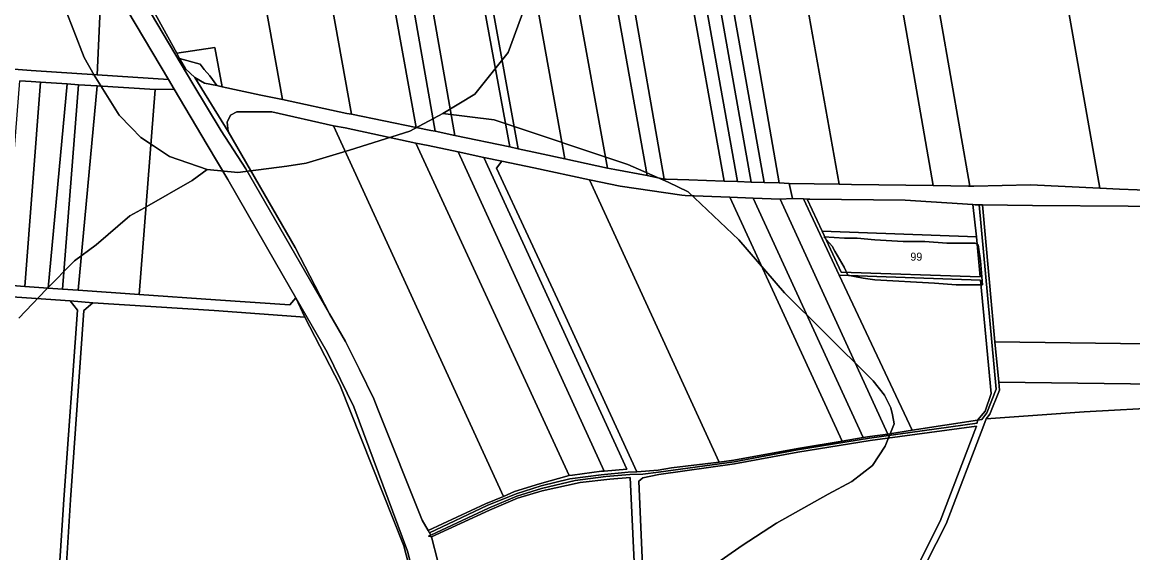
# Model space of a CAD drawing. Extents: x -541351 to -537540, y -1162694 to -1159725.
# Drawn here: x -539563 to -538870, y -1161525 to -1161193 of the extents above; entities that cross this region are included whole.
import ezdxf

# ---------------------------------------------------------------- set-up
doc = ezdxf.new("R2010")
doc.units = 0
for name, color, linetype in [('95560013', 7, 'Continuous'), ('95590013', 7, 'Continuous'), ('95610013', 7, 'Continuous'), ('95640013', 7, 'Continuous'), ('95660013', 7, 'Continuous')]:
    doc.layers.add(name, color=color, linetype=linetype)

msp = doc.modelspace()

# ---------------------------------------------------------------- linework, layer by layer
at = {"layer": '95560013'}
for points in [[(-538994.31, -1161295.03), (-539045.37, -1161294.34), (-539053.1, -1161294.23), (-539103, -1161013.98), (-539095.66, -1161011.59), (-539087.45, -1161008.9), (-539043.01, -1161015.07)], [(-539118.78, -1161021.38), (-539119.66, -1161019.55), (-539103, -1161013.98), (-539053.1, -1161294.23), (-539084.18, -1161293.8), (-539090.47, -1161293.43), (-539136.75, -1161027.11)], [(-538972.25, -1161295.43), (-538994.31, -1161295.03), (-539043.01, -1161015.07), (-539019.68, -1161018.63), (-538971.53, -1161295.41)], [(-539154.11, -1161033.45), (-539146.43, -1161030.83), (-539099.9, -1161293.1), (-539108, -1161292.84)], [(-539090.47, -1161293.43), (-539099.9, -1161293.1), (-539146.43, -1161030.83), (-539136.75, -1161027.11)], [(-539116.49, -1161292.48), (-539124.88, -1161292.22), (-539170.2, -1161038.79), (-539162.3, -1161036.06)], [(-539108, -1161292.84), (-539116.49, -1161292.48), (-539162.3, -1161036.06), (-539154.11, -1161033.45)], [(-539146.97, -1161291.52), (-539161.16, -1161290.98), (-539162.36, -1161290.96), (-539204.4, -1161050.02), (-539191.17, -1161045.44), (-539170.2, -1161038.79), (-539124.88, -1161292.22)], [(-539212.36, -1161052.68), (-539204.4, -1161050.02), (-539162.36, -1161290.96), (-539173.01, -1161288.87), (-539215.11, -1161053.62)], [(-539238.1, -1161061.49), (-539215.11, -1161053.62), (-539173.01, -1161288.87), (-539193.16, -1161285.12), (-539197.72, -1161284.19)], [(-538844.86, -1161298.63), (-538877.93, -1161297.24), (-538890.19, -1161296.72), (-538931.09, -1161065.09), (-538897.58, -1161075.44), (-538883.22, -1161083.36)], [(-539261.83, -1161069.68), (-539224.32, -1161278.28), (-539240.79, -1161274.83), (-539253.51, -1161272.15), (-539287.68, -1161083.7), (-539284.33, -1161077.27)], [(-539292.9, -1161085.27), (-539298.4, -1161081.63), (-539284.33, -1161077.27), (-539287.68, -1161083.7), (-539253.51, -1161272.15), (-539258.85, -1161270.91)], [(-539298.4, -1161081.63), (-539292.9, -1161085.27), (-539258.85, -1161270.91), (-539293.08, -1161263.8), (-539323.99, -1161088.08)], [(-539305.49, -1161261.12), (-539308.15, -1161260.59), (-539317.28, -1161258.8), (-539346.97, -1161094.08), (-539335.13, -1161091.14)], [(-539293.08, -1161263.8), (-539305.49, -1161261.12), (-539335.13, -1161091.14), (-539323.99, -1161088.08)], [(-539384.02, -1161103.38), (-539346.97, -1161094.08), (-539317.28, -1161258.8), (-539357.66, -1161250.4)], [(-539398.81, -1161106.88), (-539384.02, -1161103.38), (-539357.66, -1161250.4), (-539360.48, -1161249.96), (-539400.77, -1161241.37), (-539423.77, -1161112.8)], [(-539414.3, -1161238.64), (-539438.49, -1161233.39), (-539443.01, -1161208.8), (-539466.8, -1161212.37), (-539481.41, -1161185.77), (-539498.11, -1161150.86), (-539503.79, -1161133.46), (-539423.77, -1161112.8), (-539400.77, -1161241.37)], [(-539516.59, -1161225.93), (-539513.32, -1161157.12), (-539497.36, -1161186), (-539472.01, -1161228.75)], [(-539446.12, -1161226.55), (-539449.58, -1161222.58), (-539452.22, -1161219.18), (-539464.98, -1161215.56), (-539466.8, -1161212.37), (-539443.01, -1161208.8), (-539438.49, -1161233.39), (-539441.79, -1161232.59)], [(-539551.82, -1161230.45), (-539561.62, -1161358.04), (-539574.79, -1161357.02), (-539564.86, -1161229.58), (-539557.83, -1161230.05)], [(-539547.15, -1161359.17), (-539561.62, -1161358.04), (-539551.82, -1161230.45), (-539535.3, -1161231.55)], [(-539528.25, -1161232.02), (-539538.26, -1161359.87), (-539547.15, -1161359.17), (-539535.3, -1161231.55)], [(-539516.42, -1161232.77), (-539528.28, -1161360.42), (-539538.26, -1161359.87), (-539528.25, -1161232.02)], [(-539490.23, -1161363.16), (-539528.28, -1161360.42), (-539516.42, -1161232.77), (-539480.24, -1161235.04)], [(-539396.15, -1161369.7), (-539442.69, -1161366.45), (-539490.23, -1161363.16), (-539480.24, -1161235.04), (-539468.39, -1161234.85), (-539447.73, -1161269.69), (-539434.98, -1161291.19), (-539405.14, -1161343.09), (-539392.4, -1161365.24)], [(-539343.67, -1161428.41), (-539352.75, -1161410.03), (-539361.37, -1161392.57), (-539371.3, -1161375.32), (-539392.78, -1161333.67), (-539434.61, -1161261.23), (-539435.27, -1161255.47), (-539433.29, -1161251.13), (-539429.24, -1161248.96), (-539407.44, -1161249.02), (-539368.8, -1161257.67), (-539262.79, -1161489.32), (-539274.05, -1161494.04), (-539309.76, -1161510.68), (-539313.61, -1161504.16), (-539341.16, -1161434.73)], [(-539361.55, -1161258.93), (-539317.48, -1161268.47), (-539221.6, -1161476.34), (-539240.12, -1161481.39), (-539255.82, -1161486.31), (-539262.79, -1161489.32), (-539368.8, -1161257.67)], [(-539201.42, -1161473.62), (-539219.53, -1161475.95), (-539221.6, -1161476.34), (-539317.48, -1161268.47), (-539309.77, -1161269.96), (-539291.06, -1161274.07), (-539199.83, -1161473.45)], [(-539274.89, -1161277.57), (-539185.77, -1161472.36), (-539199.83, -1161473.45), (-539291.06, -1161274.07)], [(-539221.38, -1161478.29), (-539239.09, -1161482.82), (-539254.81, -1161487.62), (-539272.91, -1161495.1), (-539308.92, -1161512.11), (-539309.76, -1161510.68), (-539274.05, -1161494.04), (-539262.79, -1161489.32), (-539255.82, -1161486.31), (-539240.12, -1161481.39), (-539221.6, -1161476.34), (-539219.53, -1161475.95), (-539201.42, -1161473.62), (-539199.83, -1161473.45), (-539185.77, -1161472.36), (-539274.89, -1161277.57), (-539263.85, -1161279.74), (-539266.98, -1161284.14), (-539227.53, -1161369.24), (-539179.43, -1161473.91), (-539184.82, -1161474.17), (-539201.65, -1161475.75)], [(-539243.86, -1161284.07), (-539208.93, -1161291.41), (-539128, -1161467.95), (-539157.73, -1161471.56), (-539166.1, -1161473.03), (-539179.43, -1161473.91), (-539227.53, -1161369.24), (-539266.98, -1161284.14), (-539263.85, -1161279.74)], [(-539208.93, -1161291.41), (-539189.79, -1161295.41), (-539151.41, -1161301.15), (-539149.32, -1161301.23), (-539121.44, -1161302.27), (-539051.27, -1161454.8), (-539077.65, -1161459.24), (-539078.79, -1161459.42), (-539118.8, -1161466.6), (-539128, -1161467.95)], [(-539121.44, -1161302.27), (-539106.85, -1161302.97), (-539038.01, -1161452.55), (-539051.27, -1161454.8)], [(-539038.01, -1161452.55), (-539106.85, -1161302.97), (-539089.91, -1161303.49), (-539022.72, -1161450.38), (-539033.96, -1161451.91)], [(-538965.62, -1161307.06), (-538954.91, -1161422.36), (-538960.73, -1161437.13), (-538963.9, -1161441.23), (-538966.6, -1161441.62), (-538961.82, -1161436.03), (-538958.01, -1161424.97), (-538964.8, -1161354.15), (-539053.06, -1161351.04), (-539075.23, -1161303.45), (-539072.96, -1161303.55), (-539063.59, -1161323.62), (-539051.76, -1161349.11), (-538965.08, -1161352.17), (-538967.33, -1161327.07), (-538969.5, -1161306.98), (-538968, -1161307.03), (-538967.65, -1161307.04)], [(-539063.59, -1161323.62), (-539072.96, -1161303.55), (-539071.39, -1161303.57), (-539011.91, -1161304.22), (-538969.5, -1161306.98), (-538967.33, -1161327.07)], [(-538932.3, -1161307.52), (-538872.55, -1161307.97), (-538818.82, -1161309.45), (-538763.94, -1161310.7), (-538783.09, -1161395.05), (-538955.74, -1161392.63), (-538963.6, -1161307.09)], [(-538966.6, -1161441.62), (-539007.49, -1161447.85), (-539053.06, -1161351.04), (-538964.8, -1161354.15), (-538958.01, -1161424.97), (-538961.82, -1161436.03)], [(-539533.39, -1161367.17), (-539528.83, -1161372.95), (-539537.3, -1161491.19), (-539540.03, -1161532.85), (-539540.59, -1161537.62), (-539542.08, -1161542.6), (-539563.48, -1161597.18), (-539577.88, -1161634.94), (-539584.99, -1161637.27), (-539619.67, -1161612.02), (-539611.41, -1161487.28), (-539603.07, -1161362.24)], [(-539535.76, -1161531.54), (-539533.06, -1161491.37), (-539524.83, -1161373.04), (-539519.3, -1161368.27), (-539443.35, -1161373.22), (-539386.7, -1161377.26), (-539364.89, -1161419.69), (-539325.02, -1161520.27), (-539316.47, -1161553.16), (-539393.88, -1161548.37), (-539475.24, -1161542.78), (-539531.17, -1161538.46)], [(-538953.42, -1161417.83), (-538955.74, -1161392.63), (-538783.09, -1161395.05), (-538788.75, -1161420.02)], [(-538846.86, -1161433.5), (-538900.02, -1161436.5), (-538961.19, -1161440.84), (-538958.99, -1161437.99), (-538952.96, -1161422.9), (-538953.42, -1161417.83), (-538788.75, -1161420.02), (-538792.05, -1161434.55)], [(-539238.9, -1161484.33), (-539254.44, -1161489.15), (-539272.18, -1161496.58), (-539308.09, -1161513.51), (-539308.92, -1161512.11), (-539272.91, -1161495.1), (-539254.81, -1161487.62), (-539239.09, -1161482.82), (-539221.38, -1161478.29), (-539201.65, -1161475.75), (-539184.82, -1161474.17), (-539179.43, -1161473.91), (-539166.1, -1161473.03), (-539157.73, -1161471.56), (-539128, -1161467.95), (-539118.8, -1161466.6), (-539078.79, -1161459.42), (-539077.65, -1161459.24), (-539051.27, -1161454.8), (-539038.01, -1161452.55), (-539033.96, -1161451.91), (-539022.72, -1161450.38), (-539007.49, -1161447.85), (-538966.6, -1161441.62), (-538966.95, -1161443.49), (-539034.08, -1161452.94), (-539079.12, -1161460.2), (-539118.59, -1161467.64), (-539165.9, -1161474.14), (-539175.74, -1161475.47), (-539183.71, -1161475.65), (-539198.73, -1161476.82), (-539217.94, -1161479.48)], [(-539165.77, -1161475.73), (-539118.49, -1161469.02), (-539078.91, -1161461.6), (-539033.77, -1161454.46), (-538967.29, -1161445.36), (-538990.03, -1161504.88), (-539002.3, -1161529.1), (-539029.85, -1161572.32), (-539076.14, -1161579.22), (-539114.95, -1161586), (-539172.72, -1161546.83), (-539175.52, -1161542.03), (-539178.27, -1161479.78), (-539175.58, -1161477.66)], [(-539303.69, -1161529.93), (-539307.78, -1161514.67), (-539271.36, -1161497.96), (-539253.99, -1161490.48), (-539238.57, -1161485.84), (-539214.9, -1161480.72), (-539196.33, -1161478.48), (-539183.57, -1161477.43), (-539180.21, -1161547.75), (-539143.02, -1161572.92), (-539286.85, -1161613.44), (-539291.53, -1161590.26), (-539295.77, -1161569.23), (-539302.55, -1161535.61)]]:
    msp.add_lwpolyline(points, close=True, dxfattribs=at)
for points in [[(-539180.21, -1161547.75), (-539183.57, -1161477.43), (-539196.33, -1161478.48), (-539214.9, -1161480.72), (-539238.57, -1161485.84), (-539253.99, -1161490.48), (-539271.36, -1161497.96), (-539307.78, -1161514.67), (-539309.47, -1161514.21), (-539308.09, -1161513.51), (-539272.18, -1161496.58), (-539254.44, -1161489.15), (-539238.9, -1161484.33), (-539217.94, -1161479.48), (-539198.73, -1161476.82), (-539183.71, -1161475.65), (-539175.74, -1161475.47), (-539165.9, -1161474.14), (-539118.59, -1161467.64), (-539079.12, -1161460.2), (-539034.08, -1161452.94), (-538966.95, -1161443.49), (-538966.6, -1161441.62), (-538963.9, -1161441.23), (-538960.73, -1161437.13), (-538954.91, -1161422.36), (-538965.62, -1161307.06), (-538963.6, -1161307.09), (-538955.74, -1161392.63), (-538953.42, -1161417.83), (-538952.96, -1161422.9), (-538958.99, -1161437.99), (-538961.19, -1161440.84), (-538962.68, -1161444.73), (-538986.28, -1161506.51), (-538998.73, -1161531.09)], [(-539540.03, -1161532.85), (-539537.3, -1161491.19), (-539528.83, -1161372.95), (-539533.39, -1161367.17), (-539519.3, -1161368.27), (-539524.83, -1161373.04), (-539533.06, -1161491.37), (-539535.76, -1161531.54)], [(-538744.9, -1161566.45), (-538909.04, -1161586.11), (-538945.39, -1161587.98), (-538982.39, -1161591.84), (-539060.53, -1161602.73), (-539085.19, -1161606.18), (-539114.95, -1161586), (-539076.14, -1161579.22), (-539029.85, -1161572.32), (-539024.51, -1161571.52), (-538998.73, -1161531.09), (-538986.28, -1161506.51), (-538962.68, -1161444.73), (-538961.19, -1161440.84), (-538900.02, -1161436.5), (-538846.86, -1161433.5)], [(-539002.3, -1161529.1), (-538990.03, -1161504.88), (-538967.29, -1161445.36), (-539033.77, -1161454.46), (-539078.91, -1161461.6), (-539118.49, -1161469.02), (-539165.77, -1161475.73), (-539175.58, -1161477.66), (-539178.27, -1161479.78), (-539175.52, -1161542.03)]]:
    msp.add_lwpolyline(points, dxfattribs=at)
at = {"layer": '95590013'}
for points in [[(-539513.32, -1161157.12), (-539516.59, -1161225.93), (-539557.69, -1161223.11), (-539601.36, -1161219.9), (-539597.06, -1161137.85), (-539549.61, -1161136.48), (-539524.21, -1161145.9)], [(-538965.08, -1161352.17), (-539051.76, -1161349.11), (-539063.59, -1161323.62), (-538967.33, -1161327.07)]]:
    msp.add_lwpolyline(points, close=True, dxfattribs=at)
at = {"layer": '95610013'}
for points in [[(-538933.47, -1161294.66), (-538968.85, -1161295.34), (-538971.53, -1161295.41), (-539019.68, -1161018.63), (-539013.52, -1161019.58), (-538938.47, -1161062.83), (-538931.09, -1161065.09), (-538890.19, -1161296.72)], [(-539261.83, -1161069.68), (-539238.1, -1161061.49), (-539197.72, -1161284.19), (-539224.32, -1161278.28)], [(-539082.25, -1161303.24), (-539075.23, -1161303.45), (-539053.06, -1161351.04), (-539007.49, -1161447.85), (-539022.72, -1161450.38), (-539089.91, -1161303.49)]]:
    msp.add_lwpolyline(points, close=True, dxfattribs=at)
at = {"layer": '95640013'}
for points in [[(-539579.46, -1160855.53), (-539546.37, -1160976.85), (-539518.85, -1161082.11), (-539509.83, -1161115.28), (-539506.91, -1161125.99), (-539502.19, -1161143.36), (-539486.6, -1161181.18), (-539456.83, -1161231.51), (-539439.15, -1161260.76), (-539423.55, -1161284.51), (-539371.3, -1161375.32), (-539361.37, -1161392.57), (-539352.75, -1161410.03), (-539343.67, -1161428.41), (-539341.16, -1161434.73), (-539313.61, -1161504.16), (-539309.76, -1161510.68), (-539308.92, -1161512.11), (-539308.09, -1161513.51), (-539309.47, -1161514.21), (-539307.78, -1161514.67), (-539303.69, -1161529.93)], [(-539297.21, -1161624.42), (-539322.59, -1161523.59), (-539356.24, -1161433.35), (-539372.91, -1161399.14), (-539392.4, -1161365.24), (-539405.14, -1161343.09), (-539434.98, -1161291.19), (-539447.73, -1161269.69), (-539468.39, -1161234.85), (-539472.01, -1161228.75), (-539497.36, -1161186), (-539521.39, -1161121.63), (-539531.01, -1161084.78), (-539557.57, -1160980.12), (-539590.55, -1160859.01)], [(-539601.36, -1161219.9), (-539557.69, -1161223.11), (-539516.59, -1161225.93), (-539472.01, -1161228.75), (-539468.39, -1161234.85), (-539480.24, -1161235.04), (-539516.42, -1161232.77), (-539528.25, -1161232.02), (-539535.3, -1161231.55), (-539551.82, -1161230.45), (-539557.83, -1161230.05), (-539564.86, -1161229.58)], [(-538818.82, -1161309.45), (-538872.55, -1161307.97), (-538932.3, -1161307.52), (-538963.6, -1161307.09), (-538965.62, -1161307.06), (-538967.65, -1161307.04), (-538968, -1161307.03), (-538969.5, -1161306.98), (-539011.91, -1161304.22), (-539071.39, -1161303.57), (-539072.96, -1161303.55), (-539075.23, -1161303.45), (-539082.25, -1161303.24), (-539084.18, -1161293.8), (-539053.1, -1161294.23), (-539045.37, -1161294.34), (-538994.31, -1161295.03), (-538972.25, -1161295.43), (-538971.53, -1161295.41), (-538968.85, -1161295.34), (-538933.47, -1161294.66), (-538890.19, -1161296.72), (-538877.93, -1161297.24), (-538844.86, -1161298.63)], [(-539574.79, -1161357.02), (-539561.62, -1161358.04), (-539547.15, -1161359.17), (-539538.26, -1161359.87), (-539528.28, -1161360.42), (-539490.23, -1161363.16), (-539442.69, -1161366.45), (-539396.15, -1161369.7), (-539392.4, -1161365.24), (-539386.7, -1161377.26), (-539443.35, -1161373.22), (-539519.3, -1161368.27), (-539533.39, -1161367.17), (-539603.07, -1161362.24)]]:
    msp.add_lwpolyline(points, dxfattribs=at)
for points in [[(-539439.15, -1161260.76), (-539456.83, -1161231.51), (-539486.6, -1161181.18), (-539502.19, -1161143.36), (-539506.91, -1161125.99), (-539503.79, -1161133.46), (-539498.11, -1161150.86), (-539481.41, -1161185.77), (-539466.8, -1161212.37), (-539464.98, -1161215.56), (-539461.28, -1161222.06), (-539455.45, -1161227.46), (-539434.61, -1161261.23), (-539392.78, -1161333.67), (-539371.3, -1161375.32), (-539423.55, -1161284.51)], [(-539452.22, -1161219.18), (-539449.58, -1161222.58), (-539446.12, -1161226.55), (-539441.79, -1161232.59), (-539449.57, -1161231.06), (-539455.45, -1161227.46), (-539461.28, -1161222.06), (-539464.98, -1161215.56)], [(-539434.61, -1161261.23), (-539455.45, -1161227.46), (-539449.57, -1161231.06), (-539441.79, -1161232.59), (-539438.49, -1161233.39), (-539414.3, -1161238.64), (-539400.77, -1161241.37), (-539360.48, -1161249.96), (-539357.66, -1161250.4), (-539317.28, -1161258.8), (-539308.15, -1161260.59), (-539305.49, -1161261.12), (-539293.08, -1161263.8), (-539258.85, -1161270.91), (-539253.51, -1161272.15), (-539240.79, -1161274.83), (-539224.32, -1161278.28), (-539197.72, -1161284.19), (-539193.16, -1161285.12), (-539173.01, -1161288.87), (-539162.36, -1161290.96), (-539161.16, -1161290.98), (-539146.97, -1161291.52), (-539124.88, -1161292.22), (-539116.49, -1161292.48), (-539108, -1161292.84), (-539099.9, -1161293.1), (-539090.47, -1161293.43), (-539084.18, -1161293.8), (-539082.25, -1161303.24), (-539089.91, -1161303.49), (-539106.85, -1161302.97), (-539121.44, -1161302.27), (-539149.32, -1161301.23), (-539151.41, -1161301.15), (-539189.79, -1161295.41), (-539208.93, -1161291.41), (-539243.86, -1161284.07), (-539263.85, -1161279.74), (-539274.89, -1161277.57), (-539291.06, -1161274.07), (-539309.77, -1161269.96), (-539317.48, -1161268.47), (-539361.55, -1161258.93), (-539368.8, -1161257.67), (-539407.44, -1161249.02), (-539429.24, -1161248.96), (-539433.29, -1161251.13), (-539435.27, -1161255.47)], [(-539306.78, -1161596.54), (-539315.76, -1161556.43), (-539316.47, -1161553.16), (-539325.02, -1161520.27), (-539364.89, -1161419.69), (-539386.7, -1161377.26), (-539392.4, -1161365.24), (-539372.91, -1161399.14), (-539356.24, -1161433.35), (-539322.59, -1161523.59), (-539297.21, -1161624.42), (-539291.45, -1161636.72), (-539299.04, -1161627.81), (-539305.07, -1161603.34)]]:
    msp.add_lwpolyline(points, close=True, dxfattribs=at)
at = {"layer": '95660013'}
for points in [[(-539249.12, -1161183), (-539259.87, -1161212), (-539280.62, -1161238), (-539300.5, -1161250), (-539321.19, -1161261), (-539358.87, -1161273), (-539386, -1161281), (-539398.12, -1161283), (-539428.69, -1161287), (-539447.81, -1161285), (-539471.37, -1161277), (-539481.27, -1161270.33), (-539489.19, -1161265), (-539495.27, -1161258.78), (-539502.87, -1161251), (-539518.37, -1161226), (-539524.62, -1161215), (-539531.05, -1161198.33), (-539536.19, -1161185)], [(-539133.62, -1161534), (-539113.69, -1161520), (-539092.12, -1161506), (-539060, -1161488), (-539045.12, -1161480), (-539032.31, -1161470), (-539024.37, -1161458), (-539018.62, -1161444), (-539019.77, -1161438.44), (-539020.69, -1161434), (-539024.81, -1161426), (-539031.87, -1161417), (-539062.6, -1161386.44), (-539087.19, -1161362), (-539115.81, -1161329), (-539147.37, -1161299), (-539159.87, -1161293), (-539185.12, -1161282), (-539268.62, -1161254), (-539300.5, -1161250), (-539280.62, -1161238), (-539259.87, -1161212), (-539249.12, -1161183)], [(-539536.19, -1161185), (-539531.05, -1161198.33), (-539524.62, -1161215), (-539518.37, -1161226), (-539502.87, -1161251), (-539495.27, -1161258.78), (-539489.19, -1161265), (-539481.27, -1161270.33), (-539471.37, -1161277), (-539447.81, -1161285), (-539457.12, -1161292), (-539486.87, -1161309), (-539496, -1161314), (-539517.12, -1161332), (-539530.62, -1161342), (-539548.37, -1161360), (-539565.37, -1161378)], [(-539565.37, -1161378), (-539548.37, -1161360), (-539530.62, -1161342), (-539517.12, -1161332), (-539496, -1161314), (-539486.87, -1161309), (-539457.12, -1161292), (-539447.81, -1161285), (-539428.69, -1161287), (-539398.12, -1161283), (-539386, -1161281), (-539358.87, -1161273), (-539321.19, -1161261), (-539300.5, -1161250), (-539268.62, -1161254), (-539185.12, -1161282), (-539159.87, -1161293), (-539147.37, -1161299), (-539115.81, -1161329), (-539087.19, -1161362), (-539062.6, -1161386.44), (-539031.87, -1161417), (-539024.81, -1161426), (-539020.69, -1161434), (-539019.77, -1161438.44), (-539018.62, -1161444), (-539024.37, -1161458), (-539032.31, -1161470), (-539045.12, -1161480), (-539060, -1161488), (-539092.12, -1161506), (-539113.69, -1161520), (-539133.62, -1161534)]]:
    msp.add_lwpolyline(points, dxfattribs=at)
for points in [[(-538993.5, -1161356), (-538980, -1161357), (-538973.81, -1161357), (-538967.12, -1161357), (-538963.62, -1161357), (-538964.81, -1161342), (-538966.31, -1161332), (-538968.19, -1161331), (-538985.81, -1161331), (-538999.62, -1161330), (-539013.12, -1161330), (-539030.87, -1161329), (-539041.87, -1161328), (-539049.62, -1161328), (-539062.62, -1161327), (-539057.37, -1161333), (-539055.81, -1161336), (-539050, -1161346), (-539047.69, -1161351), (-539043.44, -1161351.89), (-539038.12, -1161353), (-539030.87, -1161354)], [(-539062.62, -1161327), (-539049.62, -1161328), (-539041.87, -1161328), (-539030.87, -1161329), (-539013.12, -1161330), (-538999.62, -1161330), (-538985.81, -1161331), (-538968.19, -1161331), (-538966.31, -1161332), (-538964.81, -1161342), (-538963.62, -1161357), (-538967.12, -1161357), (-538973.81, -1161357), (-538980, -1161357), (-538993.5, -1161356), (-539030.87, -1161354), (-539038.12, -1161353), (-539043.44, -1161351.89), (-539047.69, -1161351), (-539050, -1161346), (-539055.81, -1161336), (-539057.37, -1161333)]]:
    msp.add_lwpolyline(points, close=True, dxfattribs=at)

# ---------------------------------------------------------------- texts
msp.add_text('99', height=5, rotation=0, dxfattribs=at).set_placement((-539008.57, -1161342))

doc.saveas('drawing.dxf')
